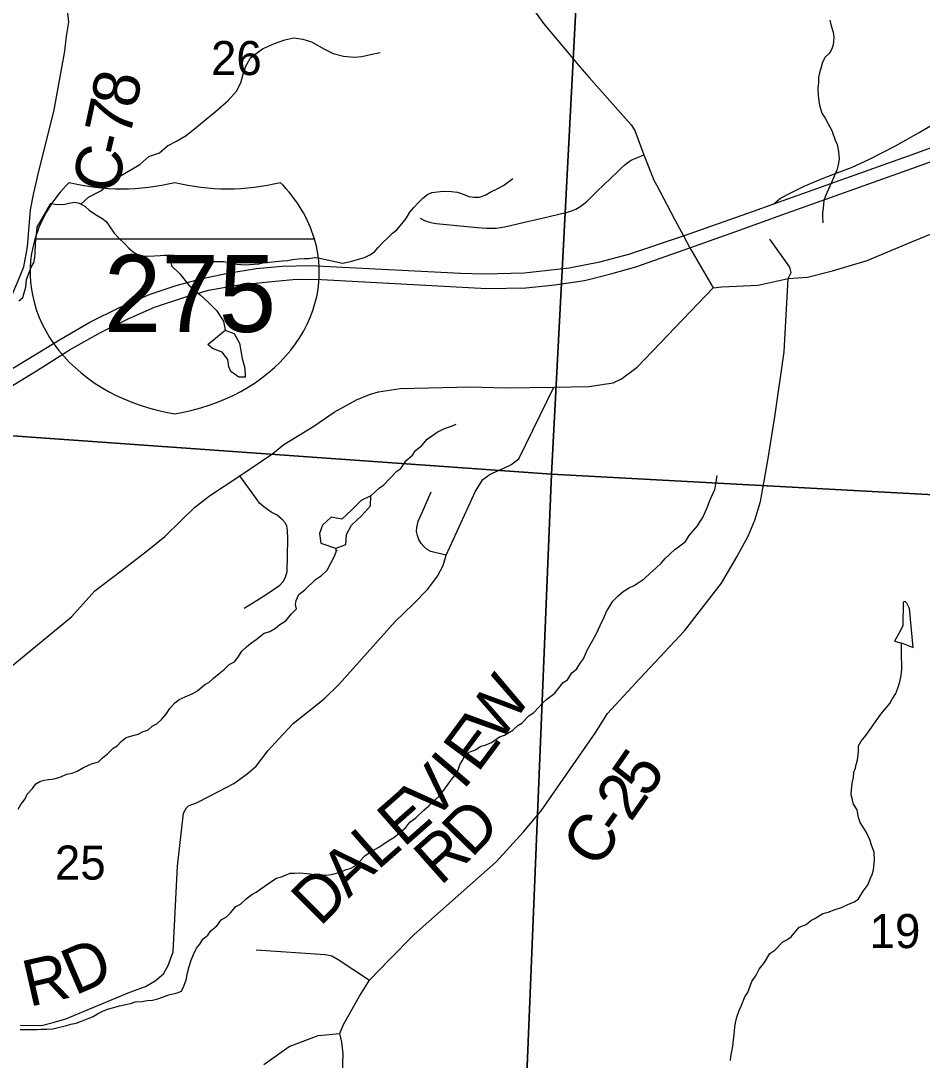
# Model space of a CAD drawing. Extents: x 0 to 34, y 0 to 22.
# Drawn here: x 6.66 to 7.766, y 17.301 to 18.576 of the extents above; entities that cross this region are included whole.
import ezdxf

# ---------------------------------------------------------------- set-up
doc = ezdxf.new("R2010")
doc.units = 0
for name, color, linetype in [('GM_X_County_Road', 7, 'Continuous'), ('GM_X_County_Road_Text', 7, 'Continuous'), ('GM_X_Interstate_Location', 7, 'Continuous'), ('GM_X_Interstate_Route', 7, 'Continuous'), ('GM_X_Interstate_Shield', 7, 'Continuous'), ('GM_X_Minor_Lake', 7, 'Continuous'), ('GM_X_Minor_River', 7, 'Continuous'), ('GM_X_Section', 7, 'Continuous'), ('GM_X_Section_Text', 7, 'Continuous'), ('GM_X_Township_Road', 7, 'Continuous')]:
    doc.layers.add(name, color=color, linetype=linetype)

msp = doc.modelspace()

# ---------------------------------------------------------------- linework, layer by layer
at = {"layer": 'GM_X_County_Road'}
msp.add_line((7.4397, 18.3749), (7.462, 18.333), dxfattribs=at)
for points in [[(6.6985, 18.7581), (6.7956, 18.7637), (6.8589, 18.773), (6.8789, 18.7716), (6.9016, 18.7697), (6.9146, 18.7712), (6.9321, 18.7752), (6.9716, 18.7869), (6.992, 18.7873), (7.0808, 18.7765), (7.0894, 18.7724), (7.0978, 18.7631), (7.1142, 18.7424), (7.1341, 18.7152), (7.1473, 18.6996), (7.1554, 18.6921), (7.1635, 18.6865), (7.2339, 18.6584), (7.2454, 18.6516), (7.2541, 18.6399), (7.2636, 18.6264), (7.3012, 18.5731), (7.3335, 18.5347)], [(6.2132, 17.9528), (6.2484, 17.9805), (6.2767, 18.0015), (6.2948, 18.0127), (6.3396, 18.0389), (6.3826, 18.0567), (6.4553, 18.094), (6.4873, 18.1117), (6.5294, 18.1364), (6.5622, 18.1557), (6.5835, 18.1719), (6.6046, 18.1941), (6.6487, 18.2393), (6.656, 18.2562), (6.6633, 18.2742), (6.6678, 18.2988), (6.6717, 18.3443), (6.6757, 18.3651), (6.6809, 18.3881), (6.7005, 18.467), (6.7138, 18.5392), (6.7158, 18.5574), (6.7186, 18.5748), (6.6985, 18.7581)], [(7.3335, 18.5347), (7.3459, 18.52), (7.3571, 18.5067), (7.402, 18.4563), (7.4086, 18.4488), (7.4133, 18.4418), (7.4243, 18.4117), (7.4365, 18.3809), (7.4397, 18.3749)], [(7.5839, 18.3515), (7.592, 18.3587), (7.6047, 18.3651), (7.6212, 18.3734), (7.6415, 18.3818), (7.6606, 18.3894), (7.6793, 18.3964), (7.702, 18.407), (7.7333, 18.4227), (7.7625, 18.4394), (7.7846, 18.4522)], [(6.5728, 17.7226), (6.722, 17.8446), (6.7504, 17.8768), (6.7829, 17.9013), (6.8151, 17.926), (6.8364, 17.9434), (6.8564, 17.9628), (6.8729, 17.9788), (6.8913, 17.9934), (6.9285, 18.0179), (6.969, 18.0451), (6.9826, 18.0562), (7.0193, 18.0788), (7.0443, 18.096), (7.0716, 18.1113), (7.0875, 18.1178), (7.0985, 18.1208), (7.1253, 18.1251), (7.2119, 18.127), (7.254, 18.1257), (7.3139, 18.1266), (7.3568, 18.1273), (7.3869, 18.132), (7.3969, 18.137), (7.416, 18.1512), (7.5095, 18.2487), (7.52, 18.2497), (7.5648, 18.252), (7.6015, 18.2599), (7.6254, 18.2618), (7.656, 18.2696), (7.6985, 18.2823), (7.7543, 18.3055), (7.8269, 18.3355)], [(7.462, 18.333), (7.4729, 18.3125), (7.4809, 18.2975), (7.5095, 18.2487)], [(7.6015, 18.2599), (7.6051, 18.2675), (7.6034, 18.2739), (7.579, 18.3085)], [(6.958, 17.2954), (6.9892, 17.3172), (7.0245, 17.3309), (7.051, 17.3335), (7.0556, 17.3443), (7.0753, 17.379), (7.0877, 17.3987), (7.1116, 17.4238), (7.1426, 17.4547), (7.2429, 17.5441), (7.2767, 17.581), (7.2984, 17.6065), (7.3645, 17.702), (7.3797, 17.7259), (7.4194, 17.769), (7.4744, 17.8276), (7.5195, 17.8862), (7.5384, 17.9186), (7.5525, 17.9436), (7.5607, 17.9635), (7.5675, 17.9864), (7.5767, 18.0367), (7.5853, 18.0903), (7.5967, 18.1701), (7.6015, 18.2599)], [(6.6593, 17.3434), (6.6851, 17.3433), (6.6993, 17.3467), (6.715, 17.3515), (6.7934, 17.3839), (6.8125, 17.3909), (6.8245, 17.3981), (6.8347, 17.4065), (6.8403, 17.4166), (6.8465, 17.4335), (6.8519, 17.5389), (6.8593, 17.6036), (6.8629, 17.6103), (6.8656, 17.6126), (6.8685, 17.6138), (6.8745, 17.616), (6.893, 17.6253), (6.9211, 17.64), (6.9375, 17.652), (6.9484, 17.6615), (6.963, 17.6804), (6.9764, 17.6951), (6.9941, 17.7139), (7.0318, 17.7439), (7.0503, 17.7623), (7.1191, 17.8391), (7.1414, 17.8604), (7.1588, 17.8784), (7.1712, 17.8945), (7.1779, 17.9078), (7.1817, 17.9203), (7.2176, 17.9991), (7.2268, 18.0133), (7.2359, 18.0199), (7.2525, 18.0274), (7.2609, 18.0313), (7.2708, 18.0385), (7.3139, 18.1266)], [(7.0481, 17.1255), (7.0507, 17.1859), (7.0521, 17.2223), (7.0536, 17.2608), (7.0555, 17.3082), (7.0537, 17.3227), (7.051, 17.3335)]]:
    msp.add_lwpolyline(points, dxfattribs=at)
at = {"layer": 'GM_X_Interstate_Route'}
for points in [[(6.4504, 18.0284), (6.6693, 18.162), (6.7092, 18.1861), (6.7443, 18.2063), (6.7809, 18.2245), (6.8184, 18.2407), (6.8502, 18.2513), (6.8807, 18.2596), (6.9138, 18.2668), (6.9485, 18.2723), (6.9803, 18.2752), (7.0149, 18.276), (7.1994, 18.2668), (7.2284, 18.2657), (7.2775, 18.267), (7.3325, 18.273), (7.3705, 18.2804), (7.406, 18.2901), (7.4729, 18.3125), (7.5591, 18.3429), (7.5839, 18.3515), (7.7536, 18.4121), (7.8043, 18.4307)], [(6.4497, 18.0066), (6.6787, 18.1466), (6.7204, 18.1727), (6.7573, 18.1936), (6.7912, 18.2107), (6.8236, 18.2248), (6.8623, 18.2375), (6.8899, 18.2457), (6.9249, 18.252), (6.9636, 18.2561), (6.9982, 18.2591), (7.0288, 18.2587), (7.2317, 18.2479), (7.2794, 18.2487), (7.3152, 18.2524), (7.3516, 18.2576), (7.384, 18.2658), (7.4146, 18.2744), (7.4809, 18.2975), (7.5416, 18.3194), (7.5893, 18.3364), (7.759, 18.397), (7.8097, 18.4157)]]:
    msp.add_lwpolyline(points, dxfattribs=at)
at = {"layer": 'GM_X_Interstate_Shield'}
msp.add_line((7.0202, 18.3083), (6.6768, 18.3083), dxfattribs=at)
msp.add_line((7.0202, 18.3083), (6.6768, 18.3083), dxfattribs=at)
for centre, start_param, end_param in [((6.8929, 18.2678), 2.47259, 2.911027), ((6.7837, 18.5477), 4.415841, 5.008937), ((6.9134, 18.5477), 4.415841, 5.008937), ((6.8041, 18.2678), 0.230566, 0.669003), ((6.8929, 18.2678), 2.911027, 4.511031), ((6.8041, 18.2678), 4.913747, 6.513751)]:
    msp.add_ellipse(centre, major_axis=(0.2219, 0), ratio=0.8, start_param=start_param, end_param=end_param, dxfattribs=at)
at = {"layer": 'GM_X_Minor_Lake'}
msp.add_line((7.028, 17.9353), (7.047, 17.9287), dxfattribs=at)
for points in [[(7.0469, 17.9247), (7.0469, 17.9291), (7.0584, 17.9337), (7.0595, 17.9459), (7.0655, 17.9571), (7.0779, 17.9689), (7.0889, 17.9812), (7.0892, 17.9933), (7.0773, 17.9876), (7.0656, 17.9757), (7.0535, 17.9647), (7.0407, 17.9669), (7.0301, 17.9573), (7.0264, 17.9471), (7.028, 17.9353)], [(7.0482, 17.9255), (7.048, 17.9261)], [(7.7405, 17.8127), (7.755, 17.807), (7.7505, 17.855), (7.7473, 17.8615), (7.745, 17.8635), (7.7428, 17.8628), (7.7424, 17.8343), (7.7391, 17.8272), (7.732, 17.8148)], [(7.732, 17.8148), (7.7409, 17.8125)]]:
    msp.add_lwpolyline(points, dxfattribs=at)
at = {"layer": 'GM_X_Minor_River'}
msp.add_line((6.889, 18.1792), (6.9105, 18.1968), dxfattribs=at)
for points in [[(7.6527, 18.577), (7.6543, 18.5701), (7.6567, 18.5624), (7.6577, 18.5559), (7.6566, 18.5464), (7.6549, 18.5412), (7.652, 18.5363), (7.6469, 18.5316), (7.6437, 18.5256), (7.642, 18.5196), (7.6398, 18.5124), (7.6389, 18.5067), (7.6386, 18.5003), (7.6381, 18.4942), (7.6385, 18.4843), (7.64, 18.4729), (7.643, 18.4629), (7.647, 18.4567), (7.6506, 18.4501), (7.6552, 18.4416), (7.659, 18.43), (7.6615, 18.4246), (7.6628, 18.4185), (7.6637, 18.4124), (7.6643, 18.4067), (7.6629, 18.3995), (7.6611, 18.3931), (7.6587, 18.3879), (7.6562, 18.3815), (7.6512, 18.3699), (7.6475, 18.3616), (7.6454, 18.3556), (7.6443, 18.3462), (7.6438, 18.3409), (7.6436, 18.3359), (7.6441, 18.3283)], [(6.7333, 18.3514), (6.7428, 18.3597), (6.7578, 18.3676), (6.7675, 18.3761), (6.78, 18.3849), (6.8058, 18.4001), (6.8168, 18.4097), (6.8298, 18.4142), (6.8395, 18.4227), (6.8507, 18.4285), (6.8627, 18.4357), (6.8752, 18.446), (6.8872, 18.4555), (6.8981, 18.4647), (6.9141, 18.4787), (6.9243, 18.4902), (6.9295, 18.5003), (6.9325, 18.5109), (6.9358, 18.5207), (6.9414, 18.5308), (6.9562, 18.5418), (6.9712, 18.5486), (6.9835, 18.5531), (6.9949, 18.5555), (7.0059, 18.5537), (7.0164, 18.5507), (7.0325, 18.5415), (7.043, 18.5362), (7.0558, 18.5328), (7.0687, 18.5317), (7.0782, 18.5326), (7.0889, 18.5349), (7.1007, 18.5373)], [(7.0245, 18.2856), (7.0543, 18.2788), (7.0642, 18.2811), (7.0727, 18.2835), (7.0815, 18.2859), (7.088, 18.2891), (7.0939, 18.2927), (7.0982, 18.2982), (7.1041, 18.3041), (7.1096, 18.3096), (7.1159, 18.3158), (7.121, 18.3198), (7.1257, 18.325), (7.1325, 18.3335), (7.1373, 18.3413), (7.1421, 18.3472), (7.1472, 18.3528), (7.1531, 18.3586), (7.1589, 18.363), (7.1643, 18.3655), (7.1781, 18.3673), (7.1883, 18.3669), (7.1951, 18.3659), (7.2007, 18.3642), (7.2094, 18.3609), (7.2158, 18.3599), (7.2226, 18.36), (7.2295, 18.3625), (7.2365, 18.3664), (7.2458, 18.371), (7.252, 18.3742), (7.2586, 18.3793), (7.2636, 18.3826)], [(6.6571, 18.2325), (6.6622, 18.2369), (6.6639, 18.2426), (6.6656, 18.2494), (6.6667, 18.2588), (6.6726, 18.2746), (6.6758, 18.2794), (6.6768, 18.2858), (6.6773, 18.2915), (6.6777, 18.3025), (6.6784, 18.3112), (6.6794, 18.318), (6.6796, 18.323), (6.6965, 18.352)], [(6.6965, 18.352), (6.7018, 18.3511), (6.712, 18.3507), (6.7186, 18.3524), (6.7258, 18.3537), (6.7311, 18.3527), (6.7382, 18.3487), (6.7437, 18.3439), (6.7515, 18.3387), (6.7589, 18.3343), (6.7645, 18.3299), (6.7681, 18.3249), (6.7742, 18.3155), (6.7801, 18.3096), (6.7867, 18.3029), (6.7922, 18.2974), (6.7977, 18.2927), (6.8029, 18.2894), (6.8089, 18.2877), (6.8162, 18.2875), (6.8306, 18.2881), (6.8359, 18.2887), (6.842, 18.2888), (6.8477, 18.2887), (6.8545, 18.2869), (6.8609, 18.2848), (6.8669, 18.283), (6.8782, 18.2823), (6.8832, 18.2817), (6.8938, 18.281), (6.9014, 18.2811), (6.9086, 18.2808), (6.9142, 18.2799), (6.9199, 18.2785), (6.9248, 18.2776), (6.9354, 18.2769), (6.9403, 18.2771), (6.9518, 18.2782), (6.9567, 18.2792), (6.9807, 18.2818), (6.9868, 18.2823), (6.9933, 18.2832), (7.0002, 18.2841), (7.0074, 18.2846), (7.0131, 18.2848), (7.0196, 18.2857), (7.0245, 18.2856)], [(6.8429, 18.2888), (6.8444, 18.2758), (6.8547, 18.2656), (6.8657, 18.252), (6.8798, 18.2402), (6.8894, 18.2308), (6.8998, 18.2206), (6.9085, 18.2075), (6.9105, 18.1968)], [(6.9105, 18.1968), (6.9216, 18.1924), (6.9282, 18.1808), (6.9314, 18.1617), (6.9345, 18.1498), (6.935, 18.1388), (6.9274, 18.139), (6.9173, 18.1457), (6.9148, 18.1515), (6.9136, 18.1607), (6.9066, 18.1696), (6.8949, 18.1741), (6.889, 18.1792)], [(7.0892, 17.9933), (7.0998, 18.0029), (7.1049, 18.0065), (7.1131, 18.0149), (7.121, 18.0234), (7.1261, 18.027), (7.1325, 18.0367), (7.1403, 18.0433), (7.1439, 18.0488), (7.1517, 18.055), (7.1584, 18.0628), (7.1705, 18.0715), (7.1798, 18.0761), (7.1882, 18.0788), (7.194, 18.0813)], [(7.2101, 17.6787), (7.2178, 17.6814), (7.2244, 17.6858), (7.2297, 17.6871), (7.2374, 17.6906), (7.2472, 17.6975), (7.2533, 17.6996), (7.2634, 17.7057), (7.2697, 17.7112), (7.2747, 17.7144), (7.2838, 17.7236), (7.2888, 17.7269), (7.2959, 17.7342), (7.3002, 17.739), (7.3053, 17.7438), (7.3151, 17.751), (7.3194, 17.7562), (7.3254, 17.764), (7.3305, 17.7676), (7.3361, 17.7761), (7.3415, 17.7805), (7.3467, 17.7883), (7.3503, 17.7931), (7.3553, 17.8047), (7.3618, 17.8163), (7.3658, 17.8234), (7.3707, 17.8342), (7.3756, 17.8443), (7.3785, 17.8511), (7.3826, 17.8578), (7.3862, 17.8641), (7.3925, 17.8703), (7.3991, 17.8758), (7.4057, 17.8798), (7.4123, 17.8833), (7.4185, 17.8873), (7.4247, 17.8916), (7.4322, 17.8982), (7.4392, 17.9044), (7.4455, 17.9107), (7.4506, 17.9162), (7.4624, 17.9272), (7.4702, 17.933), (7.4753, 17.9374), (7.4801, 17.9445), (7.4852, 17.9507), (7.4904, 17.9566), (7.4936, 17.9618), (7.4968, 17.9667), (7.5026, 17.9798), (7.5055, 17.9877), (7.5088, 17.9951), (7.5113, 18.0011), (7.5126, 18.0076), (7.5136, 18.0128), (7.5142, 18.0181)], [(6.9417, 17.8122), (6.9487, 17.8169), (6.9585, 17.8246), (6.9654, 17.8266), (6.9724, 17.8309), (6.9774, 17.8353), (6.9848, 17.84), (6.9919, 17.8485), (6.9982, 17.8547), (6.9969, 17.8597), (6.9975, 17.865), (7.0007, 17.8721), (7.0082, 17.878), (7.0215, 17.8904), (7.0289, 17.8955), (7.0356, 17.9021), (7.0408, 17.9122), (7.0445, 17.9193), (7.0469, 17.9247)], [(6.6564, 17.6085), (6.6596, 17.6145), (6.6648, 17.6212), (6.6673, 17.6272), (6.674, 17.6341), (6.678, 17.6397), (6.683, 17.6426), (6.6884, 17.6443), (6.6937, 17.6452), (6.7006, 17.6461), (6.7075, 17.6478), (6.716, 17.6517), (6.7228, 17.653), (6.7286, 17.6554), (6.7364, 17.6597), (6.7464, 17.6643), (6.7548, 17.6667), (6.7599, 17.6715), (6.7662, 17.6766), (6.7729, 17.6835), (6.7779, 17.6864), (6.7827, 17.6916), (6.7889, 17.6967), (6.7989, 17.6997), (6.8038, 17.7007), (6.8097, 17.7039), (6.8154, 17.7056), (6.8209, 17.7104), (6.8267, 17.7136), (6.8322, 17.7187), (6.8377, 17.725), (6.8425, 17.7321), (6.8488, 17.7391), (6.8539, 17.7431), (6.8612, 17.7466), (6.8709, 17.7508), (6.8767, 17.7541), (6.8853, 17.7617), (6.8903, 17.7642), (6.8962, 17.7693), (6.9032, 17.7752), (6.9091, 17.7803), (6.9154, 17.7862), (6.922, 17.7897), (6.9259, 17.7949), (6.9308, 17.8027), (6.9366, 17.8078), (6.9417, 17.8122)], [(7.5307, 17.3), (7.5313, 17.305), (7.5322, 17.3114), (7.5336, 17.3178), (7.5346, 17.3254), (7.5352, 17.3318), (7.5359, 17.3409), (7.5369, 17.3466), (7.5383, 17.3534), (7.5412, 17.3616), (7.544, 17.3668), (7.5482, 17.3785), (7.5518, 17.3837), (7.5569, 17.3972), (7.5624, 17.405), (7.5661, 17.4124), (7.5725, 17.4206), (7.5789, 17.4314), (7.5851, 17.4354), (7.595, 17.4457), (7.6, 17.4481), (7.6051, 17.4521), (7.615, 17.464), (7.6234, 17.4671), (7.6293, 17.4722), (7.6343, 17.4743), (7.644, 17.4804), (7.6505, 17.4821), (7.659, 17.4856), (7.6671, 17.488), (7.6755, 17.4919), (7.6829, 17.4951), (7.6879, 17.4987), (7.6936, 17.508), (7.6999, 17.5161), (7.7021, 17.5233), (7.7045, 17.5285), (7.7062, 17.5341), (7.7074, 17.5459), (7.707, 17.5558), (7.7039, 17.5643), (7.7022, 17.5704), (7.6976, 17.5801), (7.6936, 17.5867), (7.69, 17.5925), (7.688, 17.5986), (7.686, 17.6078), (7.6817, 17.6148), (7.6804, 17.6202), (7.6787, 17.6263), (7.6793, 17.6324), (7.6799, 17.64), (7.6817, 17.6479), (7.6823, 17.6539), (7.684, 17.6588), (7.6849, 17.6637), (7.6866, 17.669), (7.6877, 17.6796), (7.688, 17.6864), (7.6912, 17.692), (7.6967, 17.699), (7.7019, 17.7061), (7.7087, 17.7157), (7.7151, 17.7254), (7.7222, 17.7335), (7.7262, 17.7383), (7.729, 17.7435), (7.7335, 17.7506), (7.736, 17.7573), (7.7385, 17.7649), (7.7403, 17.7728), (7.7409, 17.7804), (7.7412, 17.7879), (7.7407, 17.7944), (7.7406, 17.8028), (7.7405, 17.8127)], [(6.6588, 17.3382), (6.6676, 17.3383), (6.6744, 17.3381), (6.6797, 17.3383), (6.6847, 17.3385), (6.6915, 17.3386), (6.6991, 17.3391), (6.7159, 17.3431), (6.7209, 17.3448), (6.7274, 17.3461), (6.734, 17.3486), (6.7421, 17.3517), (6.7478, 17.3538), (6.7536, 17.3574), (6.7602, 17.3609), (6.766, 17.363), (6.7737, 17.3654), (6.7809, 17.3671), (6.7943, 17.37), (6.8001, 17.3721), (6.8085, 17.3726), (6.8146, 17.3739), (6.8214, 17.3744), (6.8279, 17.3757), (6.8337, 17.3778), (6.8414, 17.3809), (6.8517, 17.3832), (6.8567, 17.3853), (6.8596, 17.3913), (6.8625, 17.3992), (6.8643, 17.4079), (6.8661, 17.4154), (6.8687, 17.4233), (6.8716, 17.4304), (6.8753, 17.4379), (6.8792, 17.4431), (6.8832, 17.449), (6.8891, 17.4542), (6.8927, 17.4593), (6.9005, 17.4659), (6.9057, 17.473), (6.9119, 17.4765), (6.917, 17.4813), (6.9237, 17.4891), (6.9291, 17.4919), (6.9362, 17.4985), (6.9432, 17.504), (6.9486, 17.5068), (6.9642, 17.5177), (6.9735, 17.5238), (6.9796, 17.5255), (6.9901, 17.5301), (6.9954, 17.5303), (7.0022, 17.5304), (7.0105, 17.5298), (7.02, 17.5283), (7.034, 17.5278), (7.0409, 17.5283), (7.047, 17.53), (7.0535, 17.5321), (7.0589, 17.5345), (7.0639, 17.5359), (7.0693, 17.5387), (7.0752, 17.5446), (7.0819, 17.5512), (7.0897, 17.5567), (7.099, 17.562), (7.104, 17.5653), (7.1106, 17.5696), (7.1176, 17.5739), (7.1243, 17.5798), (7.1321, 17.5863), (7.1372, 17.5926), (7.1443, 17.5981), (7.1545, 17.6076), (7.1603, 17.6127), (7.1741, 17.6256), (7.1808, 17.6348), (7.1864, 17.6422), (7.19, 17.647), (7.1944, 17.6526), (7.1968, 17.6582), (7.1985, 17.6631), (7.2014, 17.6679), (7.2042, 17.6732), (7.2101, 17.6787)]]:
    msp.add_lwpolyline(points, dxfattribs=at)
at = {"layer": 'GM_X_Section'}
for points in [[(6.5612, 19.0743), (7.3629, 19.0139), (7.3111, 18.02), (6.4651, 18.0799)], [(8.567, 18.9616), (8.4694, 17.9573), (7.3111, 18.02), (7.3629, 19.0139)], [(6.4651, 18.0799), (7.3111, 18.02), (7.2711, 17.0443), (6.3631, 17.0951)], [(7.3111, 18.02), (8.4694, 17.9573), (8.3778, 16.9409), (7.2711, 17.0443)]]:
    msp.add_lwpolyline(points, close=True, dxfattribs=at)
at = {"layer": 'GM_X_Township_Road'}
for points in [[(7.2779, 18.3293), (7.3065, 18.3359), (7.3218, 18.3394), (7.327, 18.3406), (7.3296, 18.3412), (7.3367, 18.3435), (7.3407, 18.3452), (7.3429, 18.3463), (7.347, 18.3487), (7.3508, 18.3515), (7.3544, 18.3546), (7.3668, 18.3667), (7.3923, 18.3915), (7.3964, 18.3954), (7.4006, 18.3993), (7.4036, 18.4018), (7.4063, 18.4038), (7.4089, 18.4053), (7.4243, 18.4117)], [(7.1499, 18.3342), (7.1553, 18.3313), (7.1587, 18.3299), (7.1631, 18.3288), (7.1694, 18.3275), (7.2202, 18.3228), (7.2311, 18.322), (7.2375, 18.3218), (7.243, 18.3217), (7.2538, 18.3234), (7.2779, 18.3293)], [(6.9339, 17.8555), (6.9496, 17.8653), (6.9621, 17.8731), (6.9775, 17.8837), (6.9815, 17.888), (6.9845, 17.8933), (6.9866, 17.9005), (6.9874, 17.9399), (6.9871, 17.9513), (6.9863, 17.9561), (6.9845, 17.9596), (6.981, 17.9639), (6.9741, 17.9694), (6.9669, 17.9734), (6.9581, 17.9796), (6.9525, 17.9844), (6.9467, 17.9923), (6.9285, 18.0179)], [(7.1817, 17.9203), (7.1696, 17.9232), (7.1628, 17.925), (7.1582, 17.9274), (7.1543, 17.9309), (7.151, 17.9346), (7.1483, 17.9397), (7.1466, 17.9447), (7.1455, 17.9495), (7.1457, 17.9546), (7.1474, 17.962), (7.1523, 17.9728), (7.1635, 17.9982)], [(6.9484, 17.436), (7.0333, 17.4301), (7.0415, 17.4285), (7.049, 17.4243), (7.0877, 17.3987)]]:
    msp.add_lwpolyline(points, dxfattribs=at)

# ---------------------------------------------------------------- texts
at = {"layer": 'GM_X_County_Road_Text'}
for s, rotation, p in [('8', 79.2108, (6.8009, 18.4674)), ('7', 77.8276, (6.7932, 18.4317)), ('-', 76.8687, (6.7877, 18.408)), ('C', 76.3121, (6.7765, 18.362)), ('W', 55.3267, (7.2469, 17.6878)), ('E', 53.4455, (7.2204, 17.6521)), ('I', 49.4961, (7.2025, 17.631)), ('5', 55.1583, (7.4283, 17.6206)), ('V', 45.6971, (7.1648, 17.5921)), ('2', 55.1024, (7.4083, 17.5918)), ('E', 41.3346, (7.1295, 17.5608)), ('D', 45.8207, (7.2127, 17.5478)), ('C', 53.5626, (7.3662, 17.5338)), ('-', 54.9657, (7.3948, 17.5726)), ('L', 41.3353, (7.0976, 17.5328)), ('R', 41.6491, (7.1746, 17.5138)), ('A', 43.6566, (7.0619, 17.4986)), ('D', 44.9916, (7.0268, 17.4635)), ('D', 23.3028, (6.7259, 17.3796)), ('R', 12.8626, (6.6698, 17.3658))]:
    msp.add_text(s, height=0.0568, rotation=rotation, dxfattribs=at).set_placement(p)
at = {"layer": 'GM_X_Interstate_Location'}
for s in ['-', '.', ',']:
    msp.add_text(s, height=0.000189, dxfattribs=at).set_placement((6.8485, 18.2417))
msp.add_text('275', height=0.000189, rotation=0, dxfattribs=at).set_placement((6.7906, 18.2025))
at = {"layer": 'GM_X_Interstate_Shield'}
msp.add_text('275', height=0.0947, dxfattribs=at).set_placement((6.7617, 18.1944))
at = {"layer": 'GM_X_Section_Text'}
for s, p in [('26', (6.8931, 18.5097)), ('25', (6.7015, 17.5222)), ('19', (7.7015, 17.4381))]:
    msp.add_text(s, height=0.04186, rotation=0, dxfattribs=at).set_placement(p)

doc.saveas('drawing.dxf')
